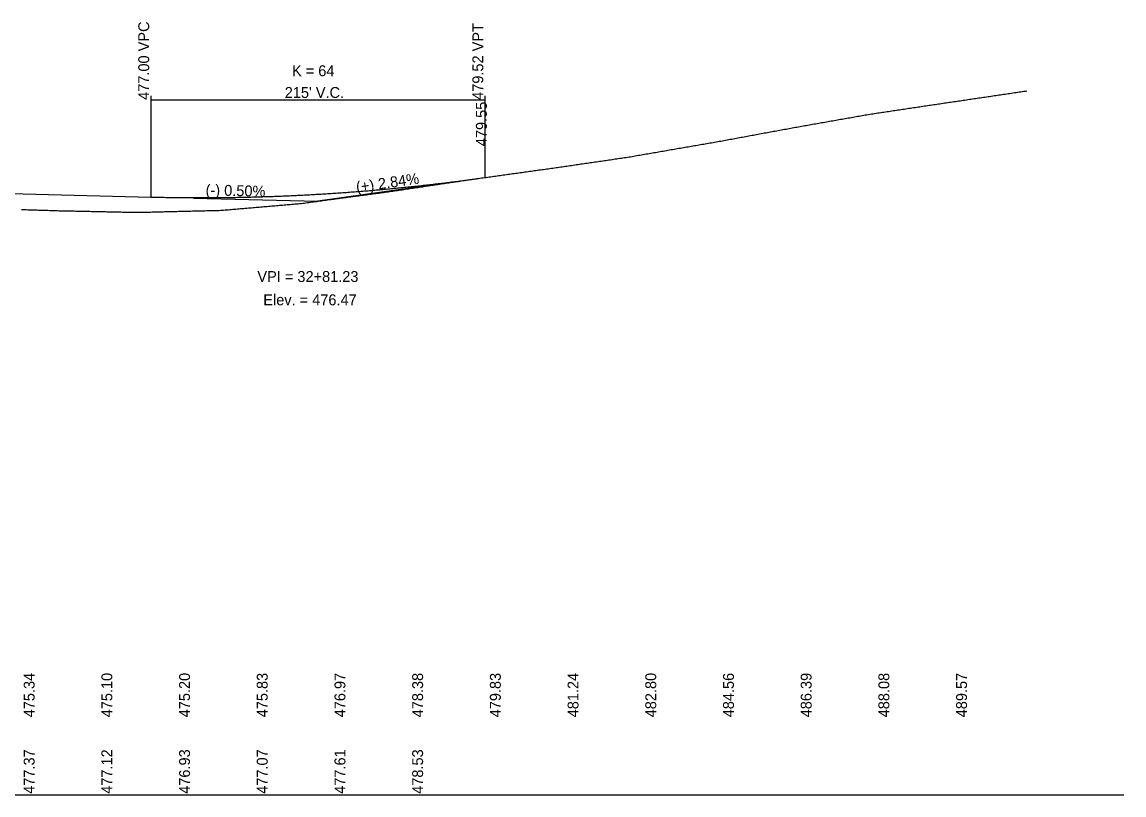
# Model space of a CAD drawing. Extents: x 1690070 to 1696783, y 823417 to 829859.
# Drawn here: x 1696074 to 1696783, y 824667 to 825164 of the extents above; entities that cross this region are included whole.
import ezdxf

# ---------------------------------------------------------------- set-up
doc = ezdxf.new("R2010")
doc.units = 0
for name, color, linetype in [('RD_DDB_GradeTX', 7, 'Continuous'), ('RD_DDB_Profile_EX', 7, 'Continuous'), ('RD_DDB_Profile_Lbl', 7, 'Continuous'), ('RD_DDB_Profile_PR', 7, 'Continuous'), ('RD_DDB_StripGrade', 7, 'Continuous'), ('RD_DDB_VCLbl', 7, 'Continuous'), ('RD_GPK_Profile_Cell', 7, 'Continuous')]:
    doc.layers.add(name, color=color, linetype=linetype)

msp = doc.modelspace()

# ---------------------------------------------------------------- linework, layer by layer
at = {"layer": 'RD_DDB_GradeTX'}
for p in [(1696343.41, 825060.35), (1696184.23, 825051.12)]:
    msp.add_line(p, (1696264.21, 825049.12), dxfattribs=at)
at = {"layer": 'RD_DDB_Profile_EX'}
for points in [[(1696622.55, 825105.62), (1696623.55, 825105.77), (1696624.55, 825105.92), (1696625.55, 825106.07), (1696626.55, 825106.22), (1696627.55, 825106.37), (1696628.55, 825106.52), (1696629.55, 825106.67), (1696630.55, 825106.82), (1696631.55, 825106.97), (1696632.55, 825107.12), (1696633.55, 825107.27), (1696634.55, 825107.42), (1696635.55, 825107.57), (1696636.55, 825107.72), (1696637.55, 825107.87), (1696638.55, 825108.02), (1696639.55, 825108.17), (1696640.55, 825108.32), (1696641.55, 825108.47), (1696642.55, 825108.62), (1696643.55, 825108.77), (1696644.55, 825108.92), (1696645.55, 825109.07), (1696646.55, 825109.22), (1696647.55, 825109.37), (1696648.55, 825109.52), (1696649.55, 825109.67), (1696650.55, 825109.82), (1696651.55, 825109.97), (1696652.55, 825110.12), (1696653.55, 825110.27), (1696654.55, 825110.42), (1696655.55, 825110.57), (1696656.55, 825110.72), (1696657.55, 825110.86), (1696658.55, 825111.01), (1696659.55, 825111.16), (1696660.55, 825111.31), (1696661.55, 825111.46), (1696662.55, 825111.61), (1696663.55, 825111.76), (1696664.55, 825111.91), (1696665.55, 825112.06), (1696666.55, 825112.2), (1696667.55, 825112.35), (1696668.55, 825112.5), (1696669.55, 825112.65), (1696670.55, 825112.79), (1696671.55, 825112.94), (1696672.55, 825113.09), (1696673.55, 825113.24), (1696674.55, 825113.38), (1696675.55, 825113.53), (1696676.55, 825113.68), (1696677.55, 825113.83), (1696678.55, 825113.98), (1696679.55, 825114.12), (1696680.55, 825114.27), (1696681.55, 825114.42), (1696682.55, 825114.57), (1696683.55, 825114.71), (1696684.55, 825114.86), (1696685.55, 825115.01), (1696686.55, 825115.16), (1696687.55, 825115.3), (1696688.55, 825115.45), (1696689.55, 825115.6), (1696690.55, 825115.75), (1696691.55, 825115.9), (1696692.55, 825116.04), (1696693.55, 825116.19), (1696694.55, 825116.34), (1696695.55, 825116.49), (1696696.55, 825116.63), (1696697.55, 825116.78), (1696698.55, 825116.93), (1696699.55, 825117.08), (1696700.55, 825117.23), (1696701.55, 825117.37), (1696702.55, 825117.52), (1696703.55, 825117.67), (1696704.55, 825117.82), (1696705.55, 825117.97), (1696706.55, 825118.11), (1696707.55, 825118.26), (1696708.55, 825118.41), (1696709.55, 825118.56), (1696710.55, 825118.71), (1696711.55, 825118.85), (1696712.55, 825119), (1696713.55, 825119.15), (1696714.55, 825119.3), (1696715.55, 825119.45), (1696716.55, 825119.59), (1696717.55, 825119.74), (1696718.55, 825119.89), (1696719.55, 825120.04), (1696720.49, 825120.18)], [(1696522.55, 825087.68), (1696523.55, 825087.86), (1696524.55, 825088.05), (1696525.55, 825088.23), (1696526.55, 825088.42), (1696527.55, 825088.6), (1696528.55, 825088.79), (1696529.55, 825088.97), (1696530.55, 825089.16), (1696531.55, 825089.34), (1696532.55, 825089.53), (1696533.55, 825089.71), (1696534.55, 825089.9), (1696535.55, 825090.08), (1696536.55, 825090.27), (1696537.55, 825090.45), (1696538.55, 825090.63), (1696539.55, 825090.82), (1696540.55, 825091), (1696541.55, 825091.19), (1696542.55, 825091.37), (1696543.55, 825091.56), (1696544.55, 825091.74), (1696545.55, 825091.92), (1696546.55, 825092.11), (1696547.55, 825092.29), (1696548.55, 825092.48), (1696549.55, 825092.66), (1696550.55, 825092.84), (1696551.55, 825093.03), (1696552.55, 825093.21), (1696553.55, 825093.39), (1696554.55, 825093.58), (1696555.55, 825093.76), (1696556.55, 825093.95), (1696557.55, 825094.13), (1696558.55, 825094.31), (1696559.55, 825094.5), (1696560.55, 825094.68), (1696561.55, 825094.86), (1696562.55, 825095.05), (1696563.55, 825095.23), (1696564.55, 825095.41), (1696565.55, 825095.6), (1696566.55, 825095.78), (1696567.55, 825095.96), (1696568.55, 825096.14), (1696569.55, 825096.33), (1696570.55, 825096.51), (1696571.55, 825096.7), (1696572.55, 825096.88), (1696573.55, 825097.06), (1696574.55, 825097.24), (1696575.55, 825097.41), (1696576.55, 825097.59), (1696577.55, 825097.77), (1696578.55, 825097.95), (1696579.55, 825098.12), (1696580.55, 825098.3), (1696581.55, 825098.48), (1696582.55, 825098.66), (1696583.55, 825098.83), (1696584.55, 825099.01), (1696585.55, 825099.19), (1696586.55, 825099.36), (1696587.55, 825099.54), (1696588.55, 825099.72), (1696589.55, 825099.89), (1696590.55, 825100.07), (1696591.55, 825100.25), (1696592.55, 825100.43), (1696593.55, 825100.6), (1696594.55, 825100.78), (1696595.55, 825100.96), (1696596.55, 825101.13), (1696597.55, 825101.31), (1696598.55, 825101.49), (1696599.55, 825101.66), (1696600.55, 825101.84), (1696601.55, 825102.01), (1696602.55, 825102.19), (1696603.55, 825102.37), (1696604.55, 825102.54), (1696605.55, 825102.72), (1696606.55, 825102.9), (1696607.55, 825103.07), (1696608.55, 825103.25), (1696609.55, 825103.43), (1696610.55, 825103.6), (1696611.55, 825103.78), (1696612.55, 825103.95), (1696613.55, 825104.13), (1696614.55, 825104.31), (1696615.55, 825104.48), (1696616.55, 825104.66), (1696617.55, 825104.83), (1696618.55, 825105), (1696619.55, 825105.16), (1696620.55, 825105.32), (1696621.55, 825105.47), (1696622.55, 825105.62)], [(1696422.55, 825071.47), (1696423.55, 825071.62), (1696424.55, 825071.77), (1696425.55, 825071.91), (1696426.55, 825072.06), (1696427.55, 825072.21), (1696428.55, 825072.35), (1696429.55, 825072.5), (1696430.55, 825072.64), (1696431.55, 825072.79), (1696432.55, 825072.94), (1696433.55, 825073.08), (1696434.55, 825073.23), (1696435.55, 825073.38), (1696436.55, 825073.52), (1696437.55, 825073.67), (1696438.55, 825073.81), (1696439.55, 825073.96), (1696440.55, 825074.11), (1696441.55, 825074.25), (1696442.55, 825074.4), (1696443.55, 825074.54), (1696444.55, 825074.69), (1696445.55, 825074.83), (1696446.55, 825074.98), (1696447.55, 825075.13), (1696448.55, 825075.27), (1696449.55, 825075.42), (1696450.55, 825075.56), (1696451.55, 825075.71), (1696452.55, 825075.85), (1696453.55, 825076), (1696454.55, 825076.14), (1696455.55, 825076.29), (1696456.55, 825076.43), (1696457.55, 825076.58), (1696458.55, 825076.72), (1696459.55, 825076.87), (1696460.55, 825077.01), (1696461.55, 825077.16), (1696462.55, 825077.31), (1696463.55, 825077.45), (1696464.55, 825077.6), (1696465.55, 825077.76), (1696466.55, 825077.94), (1696467.55, 825078.12), (1696468.55, 825078.3), (1696469.55, 825078.48), (1696470.55, 825078.66), (1696471.55, 825078.83), (1696472.55, 825079), (1696473.55, 825079.18), (1696474.55, 825079.35), (1696475.55, 825079.52), (1696476.55, 825079.7), (1696477.55, 825079.87), (1696478.55, 825080.04), (1696479.55, 825080.22), (1696480.55, 825080.39), (1696481.55, 825080.56), (1696482.55, 825080.74), (1696483.55, 825080.91), (1696484.55, 825081.08), (1696485.55, 825081.26), (1696486.55, 825081.43), (1696487.55, 825081.6), (1696488.55, 825081.78), (1696489.55, 825081.95), (1696490.55, 825082.12), (1696491.55, 825082.3), (1696492.55, 825082.47), (1696493.55, 825082.64), (1696494.55, 825082.81), (1696495.55, 825082.99), (1696496.55, 825083.16), (1696497.55, 825083.33), (1696498.55, 825083.51), (1696499.55, 825083.68), (1696500.55, 825083.85), (1696501.55, 825084.02), (1696502.55, 825084.2), (1696503.55, 825084.37), (1696504.55, 825084.54), (1696505.55, 825084.71), (1696506.55, 825084.89), (1696507.55, 825085.06), (1696508.55, 825085.23), (1696509.55, 825085.4), (1696510.55, 825085.58), (1696511.55, 825085.75), (1696512.55, 825085.92), (1696513.55, 825086.09), (1696514.55, 825086.26), (1696515.55, 825086.44), (1696516.55, 825086.61), (1696517.55, 825086.78), (1696518.55, 825086.96), (1696519.55, 825087.14), (1696520.55, 825087.31), (1696521.55, 825087.49), (1696522.55, 825087.68)], [(1696322.55, 825057.13), (1696323.55, 825057.28), (1696324.55, 825057.43), (1696325.55, 825057.58), (1696326.55, 825057.73), (1696327.55, 825057.87), (1696328.55, 825058.02), (1696329.55, 825058.17), (1696330.55, 825058.32), (1696331.55, 825058.47), (1696332.55, 825058.62), (1696333.55, 825058.77), (1696334.55, 825058.92), (1696335.55, 825059.07), (1696336.55, 825059.22), (1696337.55, 825059.37), (1696338.55, 825059.52), (1696339.55, 825059.67), (1696340.55, 825059.81), (1696341.55, 825059.96), (1696342.55, 825060.11), (1696343.55, 825060.26), (1696344.55, 825060.41), (1696345.55, 825060.56), (1696346.55, 825060.71), (1696347.55, 825060.86), (1696348.55, 825061), (1696349.55, 825061.15), (1696350.55, 825061.3), (1696351.55, 825061.45), (1696352.55, 825061.6), (1696353.55, 825061.75), (1696354.55, 825061.9), (1696355.55, 825062.04), (1696356.55, 825062.19), (1696357.55, 825062.34), (1696358.55, 825062.49), (1696359.55, 825062.64), (1696360.55, 825062.78), (1696361.55, 825062.93), (1696362.55, 825063.08), (1696363.55, 825063.22), (1696364.55, 825063.36), (1696365.55, 825063.5), (1696366.55, 825063.64), (1696367.55, 825063.78), (1696368.55, 825063.92), (1696369.55, 825064.06), (1696370.55, 825064.2), (1696371.55, 825064.34), (1696372.55, 825064.48), (1696373.55, 825064.62), (1696374.55, 825064.76), (1696375.55, 825064.9), (1696376.55, 825065.04), (1696377.55, 825065.18), (1696378.55, 825065.32), (1696379.55, 825065.46), (1696380.55, 825065.6), (1696381.55, 825065.74), (1696382.55, 825065.88), (1696383.55, 825066.02), (1696384.55, 825066.16), (1696385.55, 825066.3), (1696386.55, 825066.44), (1696387.55, 825066.57), (1696388.55, 825066.71), (1696389.55, 825066.85), (1696390.55, 825066.99), (1696391.55, 825067.13), (1696392.55, 825067.27), (1696393.55, 825067.41), (1696394.55, 825067.55), (1696395.55, 825067.69), (1696396.55, 825067.82), (1696397.55, 825067.96), (1696398.55, 825068.1), (1696399.55, 825068.24), (1696400.55, 825068.38), (1696401.55, 825068.52), (1696402.55, 825068.65), (1696403.55, 825068.79), (1696404.55, 825068.93), (1696405.55, 825069.07), (1696406.55, 825069.21), (1696407.55, 825069.35), (1696408.55, 825069.48), (1696409.55, 825069.62), (1696410.55, 825069.76), (1696411.55, 825069.9), (1696412.55, 825070.04), (1696413.55, 825070.17), (1696414.55, 825070.31), (1696415.55, 825070.45), (1696416.55, 825070.59), (1696417.55, 825070.74), (1696418.55, 825070.89), (1696419.55, 825071.03), (1696420.55, 825071.18), (1696421.55, 825071.33), (1696422.55, 825071.47)], [(1696222.55, 825045.01), (1696223.55, 825045.1), (1696224.55, 825045.19), (1696225.55, 825045.28), (1696226.55, 825045.36), (1696227.55, 825045.45), (1696228.55, 825045.54), (1696229.55, 825045.62), (1696230.55, 825045.71), (1696231.55, 825045.8), (1696232.55, 825045.88), (1696233.55, 825045.97), (1696234.55, 825046.06), (1696235.55, 825046.14), (1696236.55, 825046.23), (1696237.55, 825046.32), (1696238.55, 825046.4), (1696239.55, 825046.49), (1696240.55, 825046.58), (1696241.55, 825046.66), (1696242.55, 825046.75), (1696243.55, 825046.84), (1696244.55, 825046.92), (1696245.55, 825047.01), (1696246.55, 825047.09), (1696247.55, 825047.18), (1696248.55, 825047.27), (1696249.55, 825047.35), (1696250.55, 825047.44), (1696251.55, 825047.52), (1696252.55, 825047.61), (1696253.55, 825047.7), (1696254.55, 825047.82), (1696255.55, 825047.95), (1696256.55, 825048.09), (1696257.55, 825048.22), (1696258.55, 825048.36), (1696259.55, 825048.49), (1696260.55, 825048.63), (1696261.55, 825048.76), (1696262.55, 825048.9), (1696263.55, 825049.03), (1696264.55, 825049.17), (1696265.55, 825049.3), (1696266.55, 825049.43), (1696267.55, 825049.57), (1696268.55, 825049.7), (1696269.55, 825049.84), (1696270.55, 825049.97), (1696271.55, 825050.11), (1696272.55, 825050.24), (1696273.55, 825050.37), (1696274.55, 825050.51), (1696275.55, 825050.64), (1696276.55, 825050.78), (1696277.55, 825050.91), (1696278.55, 825051.04), (1696279.55, 825051.18), (1696280.55, 825051.31), (1696281.55, 825051.45), (1696282.55, 825051.58), (1696283.55, 825051.71), (1696284.55, 825051.85), (1696285.55, 825051.98), (1696286.55, 825052.11), (1696287.55, 825052.25), (1696288.55, 825052.38), (1696289.55, 825052.52), (1696290.55, 825052.65), (1696291.55, 825052.78), (1696292.55, 825052.92), (1696293.55, 825053.05), (1696294.55, 825053.18), (1696295.55, 825053.32), (1696296.55, 825053.45), (1696297.55, 825053.58), (1696298.55, 825053.72), (1696299.55, 825053.85), (1696300.55, 825053.98), (1696301.55, 825054.11), (1696302.55, 825054.25), (1696303.55, 825054.38), (1696304.55, 825054.51), (1696305.55, 825054.65), (1696306.55, 825054.78), (1696307.55, 825054.91), (1696308.55, 825055.04), (1696309.55, 825055.18), (1696310.55, 825055.33), (1696311.55, 825055.48), (1696312.55, 825055.63), (1696313.55, 825055.78), (1696314.55, 825055.93), (1696315.55, 825056.08), (1696316.55, 825056.23), (1696317.55, 825056.38), (1696318.55, 825056.53), (1696319.55, 825056.68), (1696320.55, 825056.83), (1696321.55, 825056.98), (1696322.55, 825057.13)], [(1696073.55, 825043.79), (1696074.55, 825043.75), (1696075.55, 825043.72), (1696076.55, 825043.69), (1696077.55, 825043.66), (1696078.55, 825043.63), (1696079.55, 825043.6), (1696080.55, 825043.57), (1696081.55, 825043.53), (1696082.55, 825043.5), (1696083.55, 825043.47), (1696084.55, 825043.44), (1696085.55, 825043.41), (1696086.55, 825043.38), (1696087.55, 825043.35), (1696088.55, 825043.31), (1696089.55, 825043.28), (1696090.55, 825043.25), (1696091.55, 825043.22), (1696092.55, 825043.19), (1696093.55, 825043.16), (1696094.55, 825043.13), (1696095.55, 825043.09), (1696096.55, 825043.06), (1696097.55, 825043.02), (1696098.55, 825042.98), (1696099.55, 825042.96), (1696100.55, 825042.94), (1696101.55, 825042.92), (1696102.55, 825042.9), (1696103.55, 825042.88), (1696104.55, 825042.86), (1696105.55, 825042.84), (1696106.55, 825042.83), (1696107.55, 825042.81), (1696108.55, 825042.79), (1696109.55, 825042.77), (1696110.55, 825042.75), (1696111.55, 825042.73), (1696112.55, 825042.7), (1696113.55, 825042.68), (1696114.55, 825042.66), (1696115.55, 825042.64), (1696116.55, 825042.62), (1696117.55, 825042.6), (1696118.55, 825042.58), (1696119.55, 825042.56), (1696120.55, 825042.54), (1696121.55, 825042.51), (1696122.55, 825042.49)], [(1696122.55, 825042.49), (1696123.55, 825042.47), (1696124.55, 825042.45), (1696125.55, 825042.43), (1696126.55, 825042.41), (1696127.55, 825042.39), (1696128.55, 825042.37), (1696129.55, 825042.35), (1696130.55, 825042.33), (1696131.55, 825042.3), (1696132.55, 825042.28), (1696133.55, 825042.26), (1696134.55, 825042.24), (1696135.55, 825042.22), (1696136.55, 825042.2), (1696137.55, 825042.18), (1696138.55, 825042.16), (1696139.55, 825042.14), (1696140.55, 825042.11), (1696141.55, 825042.09), (1696142.55, 825042.07), (1696143.55, 825042.05), (1696144.55, 825042.03), (1696145.55, 825042.01), (1696146.55, 825041.99), (1696147.55, 825041.97), (1696148.55, 825041.95), (1696149.55, 825041.96), (1696150.55, 825041.98), (1696151.55, 825042.01), (1696152.55, 825042.03), (1696153.55, 825042.06), (1696154.55, 825042.09), (1696155.55, 825042.11), (1696156.55, 825042.14), (1696157.55, 825042.17), (1696158.55, 825042.19), (1696159.55, 825042.22), (1696160.55, 825042.25), (1696161.55, 825042.27), (1696162.55, 825042.3), (1696163.55, 825042.32), (1696164.55, 825042.35), (1696165.55, 825042.38), (1696166.55, 825042.4), (1696167.55, 825042.43), (1696168.55, 825042.46), (1696169.55, 825042.48), (1696170.55, 825042.51), (1696171.55, 825042.53), (1696172.55, 825042.56), (1696173.55, 825042.58), (1696174.55, 825042.6), (1696175.55, 825042.63), (1696176.55, 825042.65), (1696177.55, 825042.68), (1696178.55, 825042.7), (1696179.55, 825042.72), (1696180.55, 825042.75), (1696181.55, 825042.77), (1696182.55, 825042.8), (1696183.55, 825042.82), (1696184.55, 825042.85), (1696185.55, 825042.87), (1696186.55, 825042.89), (1696187.55, 825042.92), (1696188.55, 825042.94), (1696189.55, 825042.97), (1696190.55, 825042.99), (1696191.55, 825043.01), (1696192.55, 825043.04), (1696193.55, 825043.06), (1696194.55, 825043.09), (1696195.55, 825043.11), (1696196.55, 825043.13), (1696197.55, 825043.16), (1696198.55, 825043.18), (1696199.55, 825043.21), (1696200.55, 825043.23), (1696201.55, 825043.26), (1696202.55, 825043.28), (1696203.55, 825043.36), (1696204.55, 825043.45), (1696205.55, 825043.54), (1696206.55, 825043.62), (1696207.55, 825043.71), (1696208.55, 825043.8), (1696209.55, 825043.88), (1696210.55, 825043.97), (1696211.55, 825044.06), (1696212.55, 825044.15), (1696213.55, 825044.23), (1696214.55, 825044.32), (1696215.55, 825044.41), (1696216.55, 825044.49), (1696217.55, 825044.58), (1696218.55, 825044.67), (1696219.55, 825044.75), (1696220.55, 825044.84), (1696221.55, 825044.93), (1696222.55, 825045.01)]]:
    msp.add_lwpolyline(points, dxfattribs=at)
at = {"layer": 'RD_DDB_Profile_PR'}
for p, q in [((1696371.71, 825064.36), (1696372.98, 825064.54)), ((1696052.98, 825054.4), (1696156.71, 825051.81))]:
    msp.add_line(p, q, dxfattribs=at)
msp.add_spline([(1696156.71, 825051.81), (1696161.01, 825051.71), (1696165.31, 825051.62), (1696169.61, 825051.55), (1696173.91, 825051.49), (1696178.21, 825051.45), (1696182.51, 825051.42), (1696186.81, 825051.41), (1696191.11, 825051.41), (1696195.41, 825051.42), (1696199.71, 825051.45), (1696204.01, 825051.49), (1696208.31, 825051.55), (1696212.61, 825051.62), (1696216.91, 825051.71), (1696221.21, 825051.81), (1696225.51, 825051.92), (1696229.81, 825052.05), (1696234.11, 825052.2), (1696238.41, 825052.35), (1696242.71, 825052.53), (1696247.01, 825052.71), (1696251.31, 825052.91), (1696255.61, 825053.13), (1696259.91, 825053.36), (1696264.21, 825053.6), (1696268.51, 825053.86), (1696272.81, 825054.13), (1696277.11, 825054.42), (1696281.41, 825054.72), (1696285.71, 825055.04), (1696290.01, 825055.37), (1696294.31, 825055.71), (1696298.61, 825056.07), (1696302.91, 825056.44), (1696307.21, 825056.83), (1696311.51, 825057.23), (1696315.81, 825057.65), (1696320.11, 825058.08), (1696324.41, 825058.52), (1696328.71, 825058.98), (1696333.01, 825059.46), (1696337.31, 825059.95), (1696341.61, 825060.45), (1696345.91, 825060.96), (1696350.21, 825061.49), (1696354.51, 825062.04), (1696358.81, 825062.6), (1696363.11, 825063.17), (1696367.41, 825063.76), (1696371.71, 825064.36)], degree=3, dxfattribs=at)
at = {"layer": 'RD_DDB_VCLbl'}
for p, q in [((1696156.71, 825116.86), (1696156.71, 825051.81)), ((1696156.71, 825114.36), (1696371.71, 825114.36)), ((1696371.71, 825116.86), (1696371.71, 825064.36))]:
    msp.add_line(p, q, dxfattribs=at)
at = {"layer": 'RD_GPK_Profile_Cell'}
msp.add_line((1695382.98, 824666.79), (1696782.98, 824666.79), dxfattribs=at)

# ---------------------------------------------------------------- texts
at = {"layer": 'RD_DDB_GradeTX'}
for s, rotation, p in [('(+) 2.84%', 8.0711, (1696289.34, 825054.7)), ('(-) 0.50%', 358.5679, (1696191.96, 825052.93))]:
    msp.add_text(s, height=7, rotation=rotation, dxfattribs=at).set_placement(p)
at = {"layer": 'RD_DDB_Profile_Lbl'}
msp.add_text('479.55', height=7, rotation=90, dxfattribs=at).set_placement((1696372.98, 825084.54))
for s, p in [('VPI = 32+81.23', (1696225.34, 824997.12)), ('Elev. = 476.47', (1696229.15, 824982.12))]:
    msp.add_text(s, height=7, dxfattribs=at).set_placement(p)
at = {"layer": 'RD_DDB_StripGrade'}
for s, p in [('477.00 VPC', (1696155.71, 825114.36)), ('479.52 VPT', (1696370.71, 825114.36)), ('475.34', (1696081.98, 824716.79)), ('475.10', (1696131.98, 824716.79)), ('475.20', (1696181.98, 824716.79)), ('475.83', (1696231.98, 824716.79)), ('476.97', (1696281.98, 824716.79)), ('478.38', (1696331.98, 824716.79)), ('479.83', (1696381.98, 824716.79)), ('481.24', (1696431.98, 824716.79)), ('482.80', (1696481.98, 824716.79)), ('484.56', (1696531.98, 824716.79)), ('486.39', (1696581.98, 824716.79)), ('488.08', (1696631.98, 824716.79)), ('489.57', (1696681.98, 824716.79)), ('477.37', (1696081.98, 824667.54)), ('477.12', (1696131.98, 824667.54)), ('476.93', (1696181.98, 824667.54)), ('477.07', (1696231.98, 824667.54)), ('477.61', (1696281.98, 824667.54)), ('478.53', (1696331.98, 824667.54))]:
    msp.add_text(s, height=7, rotation=90, dxfattribs=at).set_placement(p)
at = {"layer": 'RD_DDB_VCLbl'}
for s, p in [('K = 64', (1696247.62, 825129.61)), ("215' V.C.", (1696242.95, 825115.61))]:
    msp.add_text(s, height=7, dxfattribs=at).set_placement(p)

doc.saveas('drawing.dxf')
